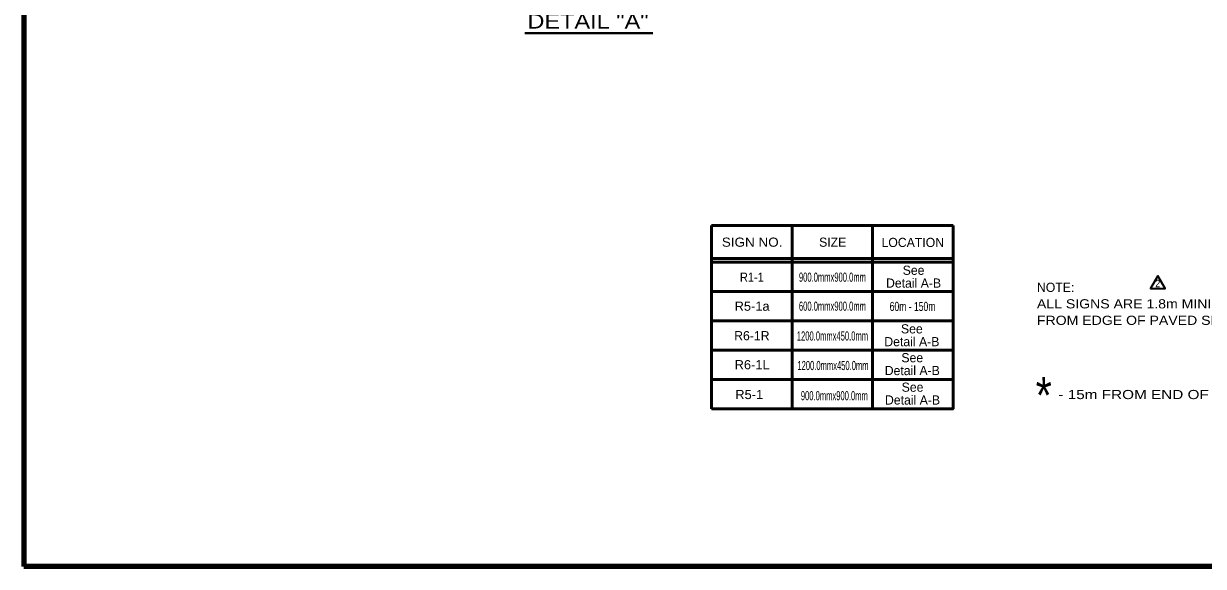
# Model space of a CAD drawing. Extents: x -198 to 658, y -402 to 142.
# Drawn here: x -140.5 to 246.2, y -390.7 to -213 of the extents above; entities that cross this region are included whole.
import ezdxf
from ezdxf.enums import TextEntityAlignment as Align

# ---------------------------------------------------------------- set-up
doc = ezdxf.new("R2010")
doc.units = 0
doc.header["$LTSCALE"] = 0.96
doc.layers.add('1', color=7, linetype='Continuous', lineweight=35)

msp = doc.modelspace()

# ---------------------------------------------------------------- linework, layer by layer
at = {"layer": '1', "lineweight": 40}
msp.add_line((23.8194, -216.0732), (65.7749, -216.0732), dxfattribs=at)
at = {"layer": '1', "lineweight": 53}
for p, q in [((85.0023, -289.8705), (85.0023, -279.0705)), ((111.4023, -339.0705), (111.4023, -279.0705)), ((137.8023, -339.0705), (137.8023, -279.0705)), ((85.0023, -289.8705), (164.2023, -289.8705)), ((85.0023, -289.8705), (85.0023, -291.0705)), ((85.0023, -291.0705), (164.2023, -291.0705)), ((85.0023, -300.6705), (85.0023, -291.0705)), ((85.0023, -300.6705), (164.2023, -300.6705)), ((85.0023, -310.2705), (85.0023, -300.6705)), ((85.0023, -310.2705), (164.2023, -310.2705)), ((85.0023, -319.8705), (85.0023, -310.2705)), ((85.0023, -319.8705), (164.2023, -319.8705)), ((85.0023, -329.4705), (164.2023, -329.4705))]:
    msp.add_line(p, q, dxfattribs=at)
at = {"layer": '1', "lineweight": 158}
msp.add_line((651.2125, -390.6704), (-140.3875, -390.6704), dxfattribs=at)
msp.add_lwpolyline([(651.2125, 135.4296), (-140.4875, 135.3296), (-140.3875, -390.6704)], dxfattribs=at)
at = {"layer": '1', "lineweight": 53}
for points in [[(164.2023, -279.0705), (164.2023, -339.0705), (85.0023, -339.0705)], [(85.0023, -279.0705), (111.4023, -279.0705), (137.8023, -279.0705), (164.2023, -279.0705)], [(85.0023, -339.0705), (85.0023, -329.4705), (85.0023, -319.8705)]]:
    msp.add_lwpolyline(points, dxfattribs=at)
at = {"layer": '1'}
msp.add_lwpolyline([(231.2895, -295.5487), (228.8895, -299.7056), (233.6895, -299.7056)], close=True, dxfattribs=at)

# ---------------------------------------------------------------- texts
for s, height, width, p in [('DETAIL "A"', 4.8, 1.2, (44.5229, -214.5917)), ('SIGN NO.', 3, 1.1, (98.3105, -286.031)), ('R1-1', 3, 0.9, (98.225, -297.4914)), ('900.0mmx900.0mm', 3, 0.6, (124.6437, -297.4914)), ('2', 2.4, 0.9, (231.2648, -299.2663)), ('R5-1a', 3, 1.05, (98.3106, -306.9848)), ('600.0mmx900.0mm', 3, 0.6, (124.6438, -306.9848)), ('60m - 150m', 3, 0.7, (150.8916, -307.0703)), ('1200.0mmx450.0mm', 3, 0.6, (124.6437, -316.7347)), ('R6-1L', 3, 1.05, (98.3106, -326.1425)), ('1200.0mmx450.0mm', 3, 0.6, (124.8213, -326.4139)), ('*', 12, 0.85, (193.8958, -340.6354)), ('R5-1', 3, 1.05, (97.3637, -335.91)), ('900.0mmx900.0mm', 3, 0.6, (125.2651, -336.2969)), ('- 15m FROM END OF RADIUS', 3, 1.25, (233.522, -335.9092))]:
    msp.add_text(s, height=height, dxfattribs=dict(at, width=width)).set_placement(p, align=Align.CENTER)
for s, p in [('SIZE', (124.7294, -286.031)), ('LOCATION', (150.9771, -286.1166)), ('See', (151.2336, -295.2204)), ('Detail A-B', (151.2336, -299.4204)), ('See', (150.6696, -314.4047)), ('R6-1R', (98.225, -316.6491)), ('Detail A-B', (150.6696, -318.6047)), ('See', (150.8106, -323.8558)), ('Detail A-B', (150.8106, -328.0558)), ('See', (150.8966, -333.5004)), ('Detail A-B', (150.8966, -337.7004))]:
    msp.add_text(s, height=3, dxfattribs=at).set_placement(p, align=Align.CENTER)
msp.add_text('NOTE:', height=3, dxfattribs=at).set_placement((191.669, -300.8154))
at = {"layer": '1', "width": 1.15}
for s, p in [('ALL SIGNS ARE 1.8m MINIMUM DISTANCE', (191.669, -306.2154)), ('FROM EDGE OF PAVED SHOULDER.', (191.669, -311.6154))]:
    msp.add_text(s, height=3, dxfattribs=at).set_placement(p)

doc.saveas('drawing.dxf')
